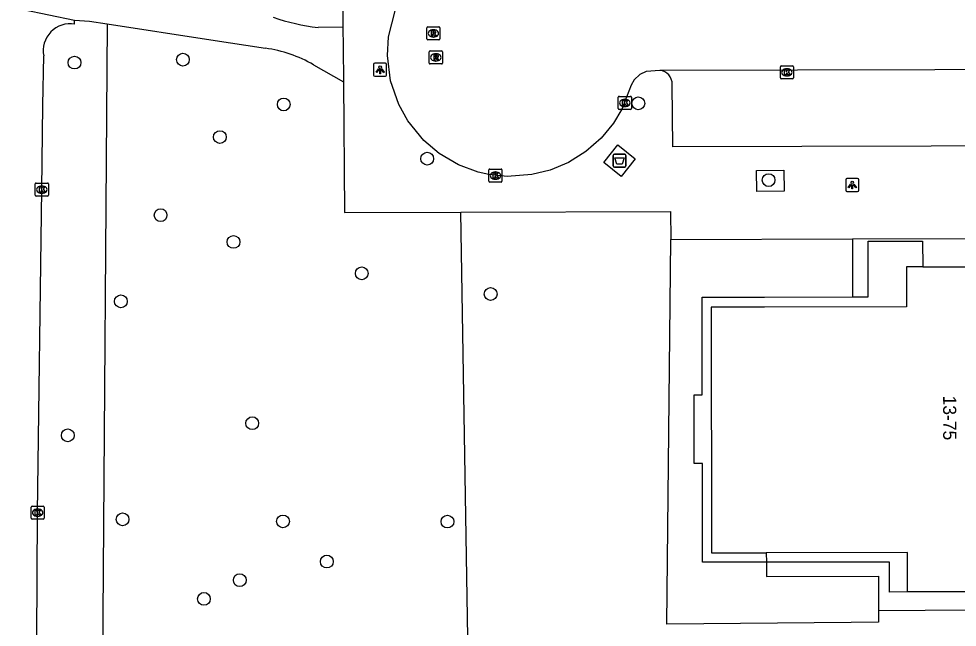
# Model space of a CAD drawing. Extents: x 160732 to 162105, y 387428 to 388479.
# Drawn here: x 160985.3 to 161057.1, y 387906.9 to 387953.5 of the extents above; entities that cross this region are included whole.
import ezdxf

# ---------------------------------------------------------------- set-up
doc = ezdxf.new("R2010")
doc.units = 0
for name, color, linetype in [('IMGEO_Afval_apart_plaats', 7, 'Continuous'), ('IMGEO_Boom', 7, 'Continuous'), ('IMGEO_Groenvoorziening', 7, 'Continuous'), ('IMGEO_Kolk', 7, 'Continuous'), ('IMGEO_Lichtpunt', 7, 'Continuous'), ('IMGEO_Loofbos', 7, 'Continuous'), ('IMGEO_Pand', 7, 'Continuous'), ('IMGEO_Pand_nummerreeks', 7, 'Continuous'), ('IMGEO_Rijbaan_lokaal_open', 7, 'Continuous'), ('IMGEO_Rioolput', 7, 'Continuous'), ('IMGEO_Voetpad_gesloten', 7, 'Continuous'), ('IMGEO_Voetpad_open', 7, 'Continuous')]:
    doc.layers.add(name, color=color, linetype=linetype)

msp = doc.modelspace()

# ---------------------------------------------------------------- linework, layer by layer
at = {"layer": 'IMGEO_Afval_apart_plaats'}
for p, q in [((161030.781, 387942.211), (161030.781, 387943.011)), ((161030.781, 387943.011), (161030.781, 387942.211)), ((161030.881, 387943.111), (161031.671, 387943.111)), ((161031.671, 387943.111), (161030.881, 387943.111)), ((161031.771, 387943.011), (161031.771, 387942.211)), ((161031.771, 387942.211), (161031.771, 387943.011)), ((161031.671, 387942.111), (161030.881, 387942.111)), ((161030.881, 387942.111), (161031.671, 387942.111))]:
    msp.add_line(p, q, dxfattribs=at)
msp.add_lwpolyline([(161030.924, 387942.825), (161031.628, 387942.825), (161031.479, 387942.355), (161031.073, 387942.355), (161030.924, 387942.825)], dxfattribs=at)
for centre, start, end in [((161030.881, 387943.011), 90, 180), ((161030.881, 387943.011), 90, 180), ((161031.671, 387943.011), 0, 90), ((161031.671, 387943.011), 360, 90), ((161030.881, 387942.211), 180, 270), ((161030.881, 387942.211), 180, 270), ((161031.671, 387942.211), 270, 0), ((161031.671, 387942.211), 270, 0)]:
    msp.add_arc(centre, 0.1, start, end, dxfattribs=at)
at = {"layer": 'IMGEO_Boom'}
for centre in [(160989.572, 387950.13), (160997.865, 387950.352), (161005.582, 387946.92), (161032.714, 387947.006), (161000.695, 387944.421), (161016.561, 387942.768), (161042.685, 387941.125), (160996.159, 387938.442), (161001.738, 387936.392), (161011.551, 387933.984), (161021.414, 387932.401), (160993.118, 387931.841), (161003.17, 387922.507), (160989.057, 387921.575), (160993.252, 387915.141), (161005.523, 387914.982), (161018.109, 387914.972), (161008.879, 387911.912), (161002.22, 387910.483), (160999.472, 387909.052)]:
    msp.add_circle(centre, 0.489, dxfattribs=at)
at = {"layer": 'IMGEO_Groenvoorziening'}
msp.add_lwpolyline([(161051.091, 387908.162), (161051.106, 387907.259), (161048.994, 387907.24), (161034.899, 387907.114), (161035.195, 387936.589)], dxfattribs=at)
at = {"layer": 'IMGEO_Kolk'}
for p, q in [((161043.583, 387948.955), (161043.583, 387949.807)), ((161043.658, 387949.881), (161044.51, 387949.881)), ((161044.584, 387949.807), (161044.584, 387948.955)), ((161044.094, 387949.101), (161044.069, 387949.101)), ((161044.071, 387949.661), (161044.096, 387949.661)), ((161044.51, 387948.881), (161043.658, 387948.881)), ((161031.182, 387946.617), (161031.182, 387947.469)), ((161031.257, 387947.543), (161032.109, 387947.543)), ((161031.67, 387947.323), (161031.695, 387947.323)), ((161032.183, 387947.469), (161032.183, 387946.617)), ((161032.109, 387946.543), (161031.257, 387946.543)), ((161031.693, 387946.763), (161031.668, 387946.763)), ((161021.282, 387941.049), (161021.282, 387941.901)), ((161021.357, 387941.975), (161022.209, 387941.975)), ((161022.283, 387941.901), (161022.283, 387941.049)), ((161021.793, 387941.195), (161021.768, 387941.195)), ((161021.77, 387941.755), (161021.795, 387941.755)), ((160986.569, 387939.977), (160986.569, 387940.829)), ((160986.644, 387940.903), (160987.496, 387940.903)), ((160987.057, 387940.683), (160987.082, 387940.683)), ((160987.57, 387940.829), (160987.57, 387939.977)), ((161022.209, 387940.975), (161021.357, 387940.975)), ((160987.496, 387939.903), (160986.644, 387939.903)), ((160987.08, 387940.123), (160987.055, 387940.123)), ((160986.248, 387915.225), (160986.248, 387916.077)), ((160986.323, 387916.151), (160987.175, 387916.151)), ((160987.249, 387916.077), (160987.249, 387915.225)), ((160986.759, 387915.371), (160986.734, 387915.371)), ((160986.736, 387915.931), (160986.761, 387915.931)), ((160987.175, 387915.151), (160986.323, 387915.151))]:
    msp.add_line(p, q, dxfattribs=at)
for points in [[(161043.583, 387948.955), (161043.583, 387949.807)], [(161043.658, 387949.881), (161044.51, 387949.881)], [(161044.584, 387949.807), (161044.584, 387948.955)], [(161043.904, 387949.581), (161044.027, 387949.581), (161044.027, 387949.43), (161044.157, 387949.581), (161044.321, 387949.581), (161044.175, 387949.43), (161044.328, 387949.181), (161044.176, 387949.181), (161044.091, 387949.345), (161044.027, 387949.278), (161044.027, 387949.181), (161043.904, 387949.181), (161043.904, 387949.581)], [(161044.51, 387948.881), (161043.658, 387948.881)], [(161031.182, 387946.617), (161031.182, 387947.469)], [(161031.257, 387947.543), (161032.109, 387947.543)], [(161031.503, 387947.243), (161031.626, 387947.243), (161031.626, 387947.092), (161031.756, 387947.243), (161031.92, 387947.243), (161031.774, 387947.092), (161031.927, 387946.843), (161031.775, 387946.843), (161031.69, 387947.007), (161031.626, 387946.94), (161031.626, 387946.843), (161031.503, 387946.843), (161031.503, 387947.243)], [(161032.183, 387947.469), (161032.183, 387946.617)], [(161032.109, 387946.543), (161031.257, 387946.543)], [(161021.282, 387941.049), (161021.282, 387941.901)], [(161021.357, 387941.975), (161022.209, 387941.975)], [(161022.283, 387941.901), (161022.283, 387941.049)], [(161021.603, 387941.675), (161021.726, 387941.675), (161021.726, 387941.524), (161021.856, 387941.675), (161022.02, 387941.675), (161021.874, 387941.524), (161022.027, 387941.275), (161021.875, 387941.275), (161021.79, 387941.439), (161021.726, 387941.372), (161021.726, 387941.275), (161021.603, 387941.275), (161021.603, 387941.675)], [(160986.569, 387939.977), (160986.569, 387940.829)], [(160986.644, 387940.903), (160987.496, 387940.903)], [(160986.89, 387940.603), (160987.013, 387940.603), (160987.013, 387940.452), (160987.143, 387940.603), (160987.307, 387940.603), (160987.161, 387940.452), (160987.314, 387940.203), (160987.162, 387940.203), (160987.077, 387940.367), (160987.013, 387940.3), (160987.013, 387940.203), (160986.89, 387940.203), (160986.89, 387940.603)], [(160987.57, 387940.829), (160987.57, 387939.977)], [(161022.209, 387940.975), (161021.357, 387940.975)], [(160987.496, 387939.903), (160986.644, 387939.903)], [(160986.248, 387915.225), (160986.248, 387916.077)], [(160986.323, 387916.151), (160987.175, 387916.151)], [(160987.249, 387916.077), (160987.249, 387915.225)], [(160986.569, 387915.851), (160986.692, 387915.851), (160986.692, 387915.7), (160986.822, 387915.851), (160986.986, 387915.851), (160986.84, 387915.7), (160986.993, 387915.451), (160986.841, 387915.451), (160986.756, 387915.615), (160986.692, 387915.548), (160986.692, 387915.451), (160986.569, 387915.451), (160986.569, 387915.851)], [(160987.175, 387915.151), (160986.323, 387915.151)]]:
    msp.add_lwpolyline(points, dxfattribs=at)
for centre, start, end in [((161043.66, 387949.805), 91.55205, 178.44795), ((161043.66, 387949.805), 91.55205, 178.44795), ((161044.508, 387949.805), 1.55205, 88.44795), ((161044.508, 387949.805), 1.55205, 88.44795), ((161043.66, 387948.957), 181.55205, 268.44795), ((161043.66, 387948.957), 181.55205, 268.44795), ((161044.508, 387948.957), 271.55205, 358.44795), ((161044.508, 387948.957), 271.55205, 358.44795), ((161031.259, 387947.467), 91.55205, 178.44795), ((161031.259, 387947.467), 91.55205, 178.44795), ((161032.107, 387947.467), 1.55205, 88.44795), ((161032.107, 387947.467), 1.55205, 88.44795), ((161031.259, 387946.619), 181.55205, 268.44795), ((161031.259, 387946.619), 181.55205, 268.44795), ((161032.107, 387946.619), 271.55205, 358.44795), ((161032.107, 387946.619), 271.55205, 358.44795), ((161021.359, 387941.899), 91.55205, 178.44795), ((161021.359, 387941.899), 91.55205, 178.44795), ((161022.207, 387941.899), 1.55205, 88.44795), ((161022.207, 387941.899), 1.55205, 88.44795), ((160986.646, 387940.827), 91.55205, 178.44795), ((160986.646, 387940.827), 91.55205, 178.44795), ((160987.494, 387940.827), 1.55205, 88.44795), ((160987.494, 387940.827), 1.55205, 88.44795), ((161021.359, 387941.051), 181.55205, 268.44795), ((161021.359, 387941.051), 181.55205, 268.44795), ((161022.207, 387941.051), 271.55205, 358.44795), ((161022.207, 387941.051), 271.55205, 358.44795), ((160986.646, 387939.979), 181.55205, 268.44795), ((160986.646, 387939.979), 181.55205, 268.44795), ((160987.494, 387939.979), 271.55205, 358.44795), ((160987.494, 387939.979), 271.55205, 358.44795), ((160986.325, 387916.075), 91.55205, 178.44795), ((160986.325, 387916.075), 91.55205, 178.44795), ((160987.173, 387916.075), 1.55205, 88.44795), ((160987.173, 387916.075), 1.55205, 88.44795), ((160986.325, 387915.227), 181.55205, 268.44795), ((160986.325, 387915.227), 181.55205, 268.44795), ((160987.173, 387915.227), 271.55205, 358.44795), ((160987.173, 387915.227), 271.55205, 358.44795)]:
    msp.add_arc(centre, 0.0765, start, end, dxfattribs=at)
for centre, major_axis, ratio, start_param, end_param in [((161044.07, 387949.381), (-0.387, 0.002), 0.722429, 4.712389, 7.853982), ((161044.095, 387949.381), (-0.39, 0.002), 0.717154, 1.570796, 4.712389), ((161031.669, 387947.043), (-0.387, 0.002), 0.722429, 4.712389, 7.853982), ((161031.694, 387947.043), (-0.39, 0.002), 0.717154, 1.570796, 4.712389), ((161021.769, 387941.475), (-0.387, 0.002), 0.722429, 4.712389, 7.853982), ((161021.794, 387941.475), (-0.39, 0.002), 0.717154, 1.570796, 4.712389), ((160987.056, 387940.403), (-0.387, 0.002), 0.722429, 4.712389, 7.853982), ((160987.081, 387940.403), (-0.39, 0.002), 0.717154, 1.570796, 4.712389), ((160986.735, 387915.651), (-0.387, 0.002), 0.722429, 4.712389, 7.853982), ((160986.76, 387915.651), (-0.39, 0.002), 0.717154, 1.570796, 4.712389)]:
    msp.add_ellipse(centre, major_axis=major_axis, ratio=ratio, start_param=start_param, end_param=end_param, dxfattribs=at)
at = {"layer": 'IMGEO_Lichtpunt'}
for p, q in [((161012.461, 387949.983), (161012.461, 387949.176)), ((161012.461, 387949.983), (161012.461, 387949.176)), ((161013.363, 387950.078), (161012.555, 387950.078)), ((161013.363, 387950.078), (161012.555, 387950.078)), ((161013.457, 387949.176), (161013.457, 387949.983)), ((161013.457, 387949.176), (161013.457, 387949.983)), ((161012.555, 387949.082), (161013.363, 387949.082)), ((161012.555, 387949.082), (161013.363, 387949.082)), ((161048.587, 387941.159), (161048.587, 387940.352)), ((161048.587, 387941.159), (161048.587, 387940.352)), ((161049.489, 387941.254), (161048.681, 387941.254)), ((161049.489, 387941.254), (161048.681, 387941.254)), ((161049.583, 387940.352), (161049.583, 387941.159)), ((161049.583, 387940.352), (161049.583, 387941.159)), ((161048.681, 387940.258), (161049.489, 387940.258)), ((161048.681, 387940.258), (161049.489, 387940.258))]:
    msp.add_line(p, q, dxfattribs=at)
for points in [[(161012.835, 387949.647), (161012.874, 387949.619), (161012.686, 387949.357), (161012.648, 387949.384), (161012.835, 387949.647)], [(161012.937, 387949.599), (161012.984, 387949.599), (161012.984, 387949.277), (161012.937, 387949.277), (161012.937, 387949.599)], [(161013.047, 387949.619), (161013.085, 387949.646), (161013.272, 387949.384), (161013.233, 387949.356), (161013.047, 387949.619)], [(161048.961, 387940.823), (161049, 387940.795), (161048.812, 387940.533), (161048.774, 387940.56), (161048.961, 387940.823)], [(161049.063, 387940.775), (161049.11, 387940.775), (161049.11, 387940.453), (161049.063, 387940.453), (161049.063, 387940.775)], [(161049.173, 387940.795), (161049.211, 387940.822), (161049.398, 387940.56), (161049.359, 387940.532), (161049.173, 387940.795)]]:
    msp.add_lwpolyline(points, dxfattribs=at)
for centre in [(161012.96, 387949.781), (161049.086, 387940.957)]:
    msp.add_circle(centre, 0.0994, dxfattribs=at)
for centre, start, end in [((161012.555, 387949.983), 90, 180), ((161012.555, 387949.983), 90, 180), ((161013.363, 387949.983), 0, 90), ((161013.363, 387949.983), 0, 90), ((161012.555, 387949.176), 180, 270), ((161012.555, 387949.176), 180, 270), ((161013.363, 387949.176), 270, 0), ((161013.363, 387949.176), 270, 360), ((161048.681, 387941.159), 90, 180), ((161048.681, 387941.159), 90, 180), ((161049.489, 387941.159), 0, 90), ((161049.489, 387941.159), 0, 90), ((161048.681, 387940.352), 180, 270), ((161048.681, 387940.352), 180, 270), ((161049.489, 387940.352), 270, 0), ((161049.489, 387940.352), 270, 360)]:
    msp.add_arc(centre, 0.0946, start, end, dxfattribs=at)
at = {"layer": 'IMGEO_Loofbos'}
for points in [[(160992.068, 387953.089), (160991.399, 387862.403)], [(161067.757, 387861.58), (161064.851, 387889.42), (161064.461, 387890.392), (161063.827, 387891.134), (161062.994, 387891.644), (161062.045, 387891.872), (161019.712, 387892.681), (161019.763, 387899.892), (161019.138, 387938.676)]]:
    msp.add_lwpolyline(points, dxfattribs=at)
at = {"layer": 'IMGEO_Pand'}
for points in [[(161054.475, 387934.485), (161053.227, 387934.484), (161053.23, 387931.409), (161042.372, 387931.399), (161038.295, 387931.395), (161038.312, 387912.581), (161042.505, 387912.585)], [(161054.475, 387934.485), (161058.548, 387934.488)], [(161053.304, 387909.581), (161053.302, 387912.594), (161042.505, 387912.585)], [(161059.335, 387909.587), (161053.304, 387909.581)]]:
    msp.add_lwpolyline(points, dxfattribs=at)
at = {"layer": 'IMGEO_Rijbaan_lokaal_open'}
for points in [[(161034.358, 387949.531), (161033.326, 387949.448), (161032.832, 387949.214), (161032.405, 387948.811), (161032.166, 387948.393), (161031.458, 387946.567), (161030.817, 387945.49), (161029.881, 387944.341), (161028.711, 387943.306), (161027.381, 387942.479), (161025.976, 387941.9), (161024.558, 387941.552), (161022.683, 387941.411), (161021.279, 387941.555), (161020.463, 387941.741), (161018.959, 387942.301), (161017.471, 387943.176), (161016.298, 387944.168), (161015.082, 387945.655), (161014.384, 387946.91), (161013.759, 387948.741), (161013.522, 387950.662), (161013.606, 387952.101), (161014.096, 387954.087)], [(161065.931, 387949.61), (161034.358, 387949.531)]]:
    msp.add_lwpolyline(points, dxfattribs=at)
at = {"layer": 'IMGEO_Rioolput'}
for p, q in [((161016.535, 387951.938), (161016.535, 387952.79)), ((161016.61, 387952.864), (161017.462, 387952.864)), ((161017.023, 387952.644), (161017.048, 387952.644)), ((161017.536, 387952.79), (161017.536, 387951.938)), ((161017.046, 387952.084), (161017.021, 387952.084)), ((161017.462, 387951.864), (161016.61, 387951.864)), ((161016.721, 387950.095), (161016.721, 387950.947)), ((161016.796, 387951.021), (161017.648, 387951.021)), ((161017.209, 387950.801), (161017.234, 387950.801)), ((161017.722, 387950.947), (161017.722, 387950.095)), ((161017.648, 387950.021), (161016.796, 387950.021)), ((161017.232, 387950.241), (161017.207, 387950.241))]:
    msp.add_line(p, q, dxfattribs=at)
for points in [[(161016.535, 387951.938), (161016.535, 387952.79)], [(161016.61, 387952.864), (161017.462, 387952.864)], [(161017.536, 387952.79), (161017.536, 387951.938)], [(161017.124, 387952.562), (161016.872, 387952.564), (161016.872, 387952.164)], [(161016.872, 387952.164), (161016.996, 387952.164), (161016.996, 387952.326), (161017.007, 387952.326)], [(161017.05, 387952.483), (161016.996, 387952.483), (161016.996, 387952.402)], [(161016.996, 387952.402), (161017.048, 387952.402)], [(161017.054, 387952.297), (161017.125, 387952.164), (161017.265, 387952.164), (161017.2, 387952.29)], [(161017.462, 387951.864), (161016.61, 387951.864)], [(161016.721, 387950.095), (161016.721, 387950.947)], [(161016.796, 387951.021), (161017.648, 387951.021)], [(161017.31, 387950.719), (161017.058, 387950.721), (161017.058, 387950.321)], [(161017.058, 387950.321), (161017.182, 387950.321), (161017.182, 387950.483), (161017.193, 387950.483)], [(161017.236, 387950.64), (161017.182, 387950.64), (161017.182, 387950.559)], [(161017.182, 387950.559), (161017.234, 387950.559)], [(161017.722, 387950.947), (161017.722, 387950.095)], [(161017.648, 387950.021), (161016.796, 387950.021)], [(161017.24, 387950.454), (161017.311, 387950.321), (161017.451, 387950.321), (161017.386, 387950.447)]]:
    msp.add_lwpolyline(points, dxfattribs=at)
for centre, radius, start, end in [((161016.612, 387952.788), 0.0765, 91.55205, 178.44795), ((161016.612, 387952.788), 0.0765, 91.55205, 178.44795), ((161017.46, 387952.788), 0.0765, 1.55205, 88.44795), ((161017.46, 387952.788), 0.0765, 1.55205, 88.44795), ((161016.612, 387951.94), 0.0765, 181.55205, 268.44795), ((161016.612, 387951.94), 0.0765, 181.55205, 268.44795), ((161017.006, 387952.273), 0.0533, 26.02933, 88.69889), ((161017.032, 387952.591), 0.19, 274.7715, 282.96867), ((161017.056, 387952.387), 0.0964, 77.00612, 93.18647), ((161017.07, 387952.444), 0.0378, 276.66336, 79.67722), ((161017.123, 387952.452), 0.109, 350.36119, 89.41601), ((161017.121, 387952.452), 0.112, 277.58423, 350.98172), ((161017.105, 387952.237), 0.108, 29.51342, 73.79051), ((161017.46, 387951.94), 0.0765, 271.55205, 358.44795), ((161017.46, 387951.94), 0.0765, 271.55205, 358.44795), ((161016.798, 387950.945), 0.0765, 91.55205, 178.44795), ((161016.798, 387950.945), 0.0765, 91.55205, 178.44795), ((161017.192, 387950.43), 0.0533, 26.02933, 88.69889), ((161017.218, 387950.748), 0.19, 274.7715, 282.96867), ((161017.242, 387950.544), 0.0964, 77.00612, 93.18647), ((161017.256, 387950.601), 0.0378, 276.66336, 79.67722), ((161017.309, 387950.609), 0.109, 350.36119, 89.41601), ((161017.307, 387950.609), 0.112, 277.58423, 350.98172), ((161017.291, 387950.394), 0.108, 29.51342, 73.79051), ((161017.646, 387950.945), 0.0765, 1.55205, 88.44795), ((161017.646, 387950.945), 0.0765, 1.55205, 88.44795), ((161016.798, 387950.097), 0.0765, 181.55205, 268.44795), ((161016.798, 387950.097), 0.0765, 181.55205, 268.44795), ((161017.646, 387950.097), 0.0765, 271.55205, 358.44795), ((161017.646, 387950.097), 0.0765, 271.55205, 358.44795)]:
    msp.add_arc(centre, radius, start, end, dxfattribs=at)
for centre, major_axis, ratio, start_param, end_param in [((161017.022, 387952.364), (-0.387, 0.002), 0.722429, 4.712389, 7.853982), ((161017.047, 387952.364), (-0.39, 0.002), 0.717154, 1.570796, 4.712389), ((161017.208, 387950.521), (-0.387, 0.002), 0.722429, 4.712389, 7.853982), ((161017.233, 387950.521), (-0.39, 0.002), 0.717154, 1.570796, 4.712389)]:
    msp.add_ellipse(centre, major_axis=major_axis, ratio=ratio, start_param=start_param, end_param=end_param, dxfattribs=at)
at = {"layer": 'IMGEO_Voetpad_gesloten'}
for points in [[(160983.661, 387954.594), (160989.581, 387953.371)], [(160989.583, 387953.081), (160989.581, 387953.371)], [(160989.581, 387953.371), (160990.719, 387953.297), (160992.068, 387953.089)], [(160992.068, 387953.089), (161000, 387951.868), (161004.178, 387951.225)], [(161010.109, 387952.836), (161008.206, 387952.81)], [(161010.109, 387952.836), (161010.122, 387951.306), (161010.145, 387948.657)], [(160986.678, 387864.414), (160986.624, 387891.449), (160986.747, 387915.651), (160987.068, 387940.403), (160987.142, 387946.868), (160987.213, 387950.635)], [(161007.86, 387949.963), (161010.145, 387948.657)], [(161031.15, 387943.825), (161032.479, 387942.744), (161031.405, 387941.396), (161030.071, 387942.481), (161031.15, 387943.825)]]:
    msp.add_lwpolyline(points, dxfattribs=at)
for centre, radius, start, end in [((161010.232, 387969.434), 16.747, 250.98329, 263.05187), ((160989.251, 387951.031), 2.077, 80.81138, 190.99681), ((161002.73, 387940.998), 10.329, 60.22046, 81.94139)]:
    msp.add_arc(centre, radius, start, end, dxfattribs=at)
at = {"layer": 'IMGEO_Voetpad_open'}
for points in [[(161065.909, 387963.585), (161049.31, 387963.534), (161047.618, 387963.529), (161032.769, 387963.484), (161030.521, 387963.477), (161009.997, 387963.415), (161010.109, 387952.836)], [(161010.145, 387948.657), (161010.243, 387938.657), (161019.138, 387938.676)], [(161065.007, 387943.759), (161035.35, 387943.68), (161035.309, 387948.462)], [(161041.769, 387941.864), (161043.857, 387941.887), (161043.884, 387940.277), (161041.793, 387940.257), (161041.769, 387941.864)], [(161019.138, 387938.676), (161035.174, 387938.711), (161035.195, 387936.589)], [(161035.195, 387936.589), (161049.092, 387936.626)], [(161049.092, 387936.626), (161058.542, 387936.652)], [(161049.092, 387936.626), (161049.095, 387932.178)], [(161049.095, 387932.178), (161050.315, 387932.179), (161050.312, 387936.438), (161054.473, 387936.441), (161054.475, 387934.485)], [(161042.517, 387911.855), (161037.627, 387911.851), (161037.62, 387919.417), (161036.98, 387919.417), (161036.976, 387924.69), (161037.606, 387924.691), (161037.599, 387932.168), (161042.377, 387932.172), (161049.095, 387932.178)], [(161042.505, 387912.585), (161042.517, 387911.855)], [(161053.304, 387909.581), (161051.936, 387909.56), (161051.934, 387911.863), (161042.517, 387911.855)], [(161042.517, 387911.855), (161042.534, 387910.767), (161051.089, 387910.801), (161051.091, 387908.162)], [(161051.091, 387908.162), (161061.797, 387908.247), (161065.212, 387908.27)]]:
    msp.add_lwpolyline(points, dxfattribs=at)
msp.add_arc((161034.249, 387948.476), 1.06, 359.2319, 84.08174, dxfattribs=at)

# ---------------------------------------------------------------- texts
at = {"layer": 'IMGEO_Pand_nummerreeks'}
msp.add_text('13-75', height=1, rotation=270.05136, dxfattribs=at).set_placement((161056.042, 387924.62))

doc.saveas('drawing.dxf')
